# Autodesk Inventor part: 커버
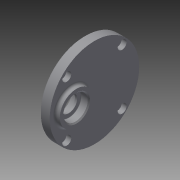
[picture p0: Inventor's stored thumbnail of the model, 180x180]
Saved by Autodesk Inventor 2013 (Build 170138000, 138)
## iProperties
Created: 2015-07
Part Number: 커버
Material: 일반
Document SubType Name: Modeling
Designer: user
Density: 1 g/cm^3
Author: user
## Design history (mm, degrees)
sketch "스케치1"
  geometry: C1 r 40 at (0, 0); 1 further point
  constraints: 1 centre point, 1 coincident
  dimensions: "d0" = 80 diameter of C1
extrude "돌출1" new body sketch "스케치1" distance "d1" = 9; taper "d2" = 0 deg
sketch "스케치2"
  geometry: L1 (0, 0)-(0, 11); L2 (0, 0)-(0, -20); C1 r 40 at (0, 0) reference; C2 r 14 at (0, 11); C3 r 14 at (0, -20)
  constraints: 4 end point, 2 centre point, 2 coincident, 1 collinear, 1 vertical
  dimensions: "d3" = 11 distance of L1.start L1.end; "d4" = 20 distance of L1.start L2.end; "d5" = 28 diameter of C2; "d6" = 28 diameter of C3
extrude "돌출2" join sketch "스케치2" distance "d7" = 3; taper "d8" = 0 deg
sketch "스케치3"
  geometry: L1 (0, 0)-(0, -20); C1 r 40 at (0, 0) reference; C2 r 15 at (0, -20)
  constraints: 2 end point, 1 centre point, 1 coincident, 1 vertical
  dimensions: "d9" = 20 distance of L1.start L1.end; "d10" = 30 diameter of C2
extrude "돌출3" join sketch "스케치3" distance "d11" = 4; taper "d12" = 0 deg
sketch "스케치4"
  geometry: C1 r 15 at (0, 0) reference; C2 r 11 at (0, 0); 1 further point
  constraints: 1 centre point, 1 coincident
  dimensions: "d13" = 22 diameter of C2
extrude "돌출4" cut sketch "스케치4" distance "d14" = 7; taper "d15" = 0 deg
sketch "스케치5"
  geometry: C1 r 14 at (0, 0) reference; C2 r 11 at (0, 0); 1 further point
  constraints: 1 centre point, 1 coincident
  dimensions: "d16" = 22 diameter of C2
extrude "돌출5" cut sketch "스케치5" distance "d17" = 7; taper "d18" = 0 deg
sketch "스케치6"
  geometry: C1 r 11 at (0, 0) reference; C2 r 7.5 at (0, 0); 1 further point
  constraints: 1 centre point, 1 coincident
  dimensions: "d19" = 15 diameter of C2
extrude "돌출6" cut sketch "스케치6" distance "d20" = 2; taper "d21" = 0 deg
sketch "스케치7"
  geometry: C1 r 14 at (0, 0) reference; C2 r 11 at (0, 0); 1 further point
  constraints: 1 centre point, 1 coincident
  dimensions: "d22" = 22 diameter of C2
extrude "돌출7" cut sketch "스케치7" distance "d23" = 7; taper "d24" = 0 deg
sketch "스케치8"
  geometry: C1 r 9 at (0, 0); 2 further points
  constraints: 1 centre point, 1 coincident, 1 vertical alignment
  dimensions: "d25" = 18 diameter of C1
extrude "돌출8" cut sketch "스케치8" distance "d26" = 1; taper "d27" = 0 deg
fillet "모깎기1" dims "d28" = 2
fillet "모깎기2" dims "d29" = 0.3
chamfer "모따기1" distance "d30" = 1; stored, may be unused: second distance "d31" = 2, angle "d32" = 45 deg
chamfer "모따기2" distance "d33" = 1; stored, may be unused: second distance "d34" = 2, angle "d35" = 45 deg
fillet "모깎기3" dims "d36" = 2
chamfer "모따기3" distance "d37" = 1; stored, may be unused: second distance "d38" = 2, angle "d39" = 45 deg
sketch "스케치9" dims "d40" = 70
  geometry: L1 (0, 0)-(24.749, 24.749); L2 (0, 0)-(35, 0); C1 r 40 at (0, 0) reference; C2 r 4 at (24.749, 24.749)
  constraints: 4 end point, 2 coincident, 1 centre point, 1 equal length, 1 horizontal, 3 other
  dimensions: "d41" = 45 deg angle of L2 L1; "d42" = 8 diameter of C2
extrude "돌출9" cut sketch "스케치9" distance "d43" = 4.4; taper "d44" = 0 deg
sketch "스케치10"
  geometry: C1 r 4 at (0, 0) reference; C2 r 2.25 at (0, 0); 1 further point
  constraints: 1 centre point, 1 coincident
  dimensions: "d45" = 4.5 diameter of C2
extrude "돌출10" cut sketch "스케치10" stored distance "d46" = 4.4; taper "d47" = 0 deg
fillet "모깎기4" dims "d51" = 0.3
node "솔리드1"
pattern_circular "원형 패턴1" dims angle "d49" = 360 deg
